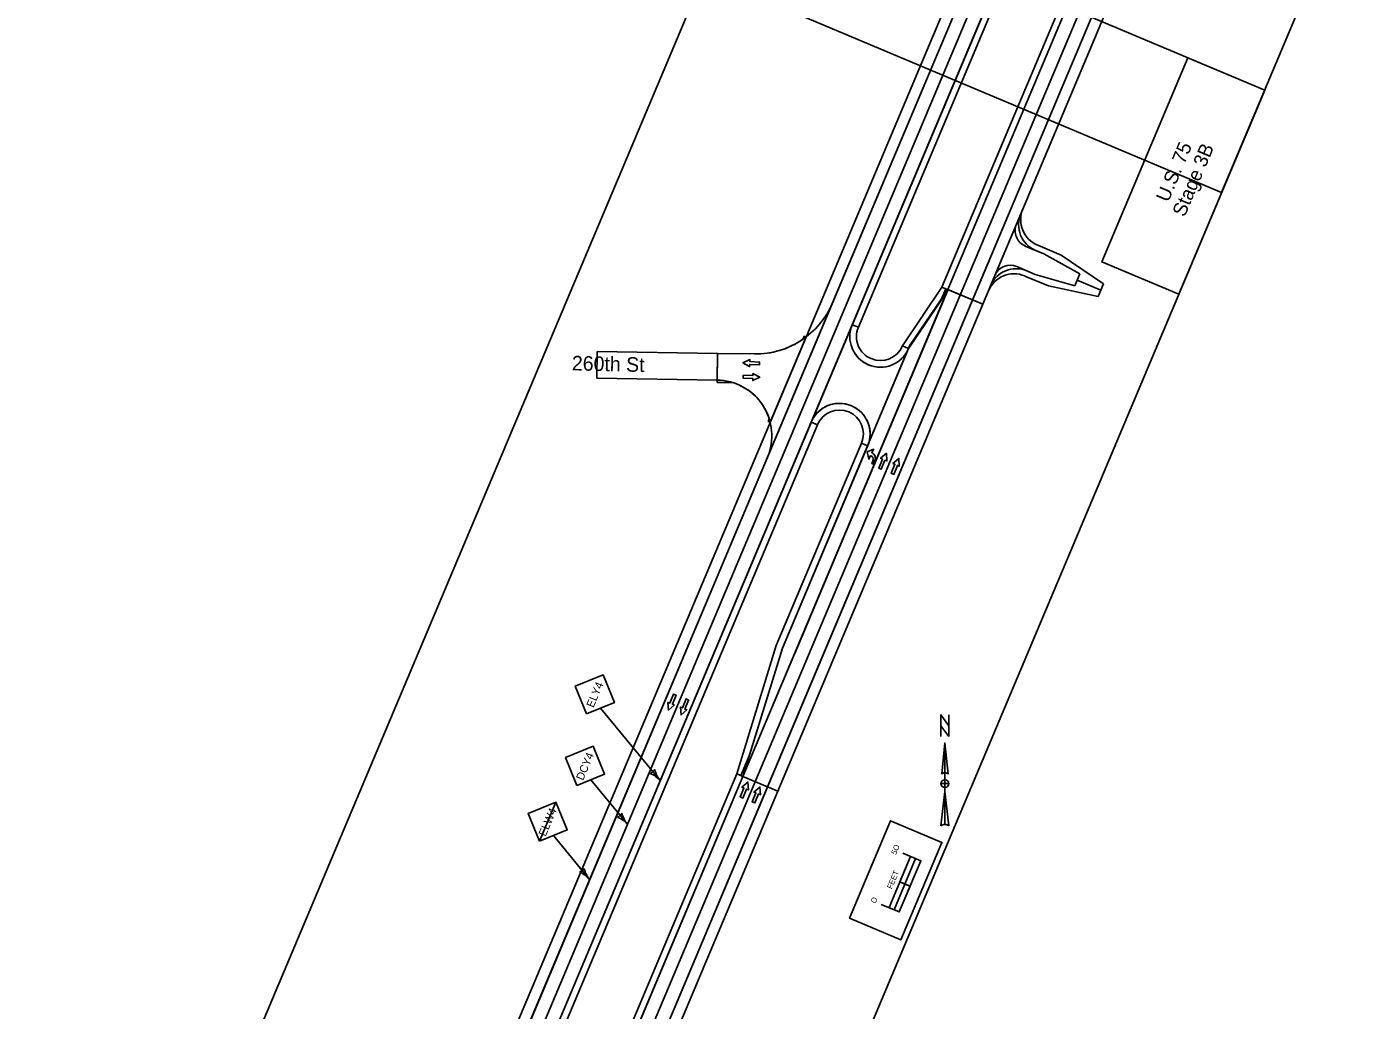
# Model space of a CAD drawing. Extents: x 14104283 to 14120882, y 8635219 to 8671666.
# Drawn here: x 14112889 to 14114078, y 8655411 to 8656296 of the extents above; entities that cross this region are included whole.
import ezdxf

# ---------------------------------------------------------------- set-up
doc = ezdxf.new("R2010")
doc.units = 0
for name, color, linetype in [('Cell', 7, 'Continuous'), ('dsnCellsNorthArrow', 7, 'Continuous'), ('dsnCellsScaleBlock', 7, 'Continuous'), ('dsnNonPlotable', 7, 'Continuous'), ('dsnPaintExistingBrokenLaneLineWhite', 7, 'Continuous'), ('dsnPaintExistingEdgeLineLeftYellow', 7, 'Continuous'), ('dsnPaintExistingEdgeLineRightWhite', 7, 'Continuous'), ('dsnPaintExistingLaneLineWhite', 7, 'Continuous'), ('dsnShadingGranular', 7, 'Continuous'), ('dsnShadingPaved', 7, 'Continuous'), ('dsnStdLabel', 7, 'Continuous'), ('dsnStgShadingPrevPav', 7, 'Continuous'), ('dsnTextFinalPlan', 7, 'Continuous'), ('dsnTextOverlapEven', 7, 'Continuous')]:
    doc.layers.add(name, color=color, linetype=linetype)

msp = doc.modelspace()

# ---------------------------------------------------------------- linework, layer by layer
at = {"layer": 'Cell'}
for p, q in [((14113648.5, 8655910.1), (14113648.2, 8655910.2)), ((14113649.3, 8655912.6), (14113649.4, 8655912.5))]:
    msp.add_line(p, q, dxfattribs=at)
for points in [[(14113548.3, 8655994.3), (14113548.2, 8655991.8), (14113539.5, 8655992.2), (14113539.4, 8655990.3), (14113533.3, 8655993.7), (14113539.7, 8655996.5), (14113539.6, 8655994.7)], [(14113533.5, 8655979.9), (14113533.6, 8655982.4), (14113542.3, 8655982.1), (14113542.4, 8655984), (14113548.5, 8655980.6), (14113542.2, 8655977.7), (14113542.2, 8655979.6)], [(14113657.8, 8655898), (14113655.5, 8655899), (14113658.8, 8655907.1), (14113657.1, 8655907.8), (14113662.4, 8655912.4), (14113662.9, 8655905.4), (14113661.1, 8655906.1)], [(14113669, 8655893.3), (14113666.7, 8655894.3), (14113670, 8655902.4), (14113668.3, 8655903.1), (14113673.5, 8655907.7), (14113674, 8655900.7), (14113672.3, 8655901.4)], [(14113470.9, 8655695.7), (14113473.2, 8655694.7), (14113469.9, 8655686.6), (14113471.6, 8655685.9), (14113466.3, 8655681.3), (14113465.8, 8655688.3), (14113467.5, 8655687.6)], [(14113482.2, 8655691.4), (14113484.5, 8655690.4), (14113481.2, 8655682.3), (14113482.9, 8655681.6), (14113477.7, 8655677), (14113477.1, 8655684), (14113478.9, 8655683.3)], [(14113533.3, 8655602.2), (14113530.9, 8655603.2), (14113534.3, 8655611.2), (14113532.5, 8655612), (14113537.8, 8655616.6), (14113538.3, 8655609.6), (14113536.6, 8655610.3)], [(14113544.1, 8655597.8), (14113541.7, 8655598.7), (14113545.1, 8655606.8), (14113543.3, 8655607.5), (14113548.6, 8655612.1), (14113549.1, 8655605.2), (14113547.4, 8655605.9)]]:
    msp.add_lwpolyline(points, close=True, dxfattribs=at)
for points in [[(14113539.6, 8655994.7), (14113539.7, 8655996.5), (14113533.3, 8655993.7), (14113539.4, 8655990.3), (14113539.5, 8655992.2), (14113548.2, 8655991.8), (14113548.3, 8655994.3), (14113539.6, 8655994.7)], [(14113542.2, 8655979.6), (14113542.2, 8655977.7), (14113548.5, 8655980.6), (14113542.4, 8655984), (14113542.3, 8655982.1), (14113533.6, 8655982.4), (14113533.5, 8655979.9), (14113542.2, 8655979.6)], [(14113645.1, 8655913.7), (14113650.8, 8655915.9), (14113649.3, 8655912.6)], [(14113645.1, 8655913.7), (14113650.8, 8655915.9), (14113649.3, 8655912.6)], [(14113648.2, 8655910.2), (14113646.6, 8655906.9), (14113645.1, 8655913.7)], [(14113648.2, 8655910.2), (14113646.6, 8655906.9), (14113645.1, 8655913.7)], [(14113648.5, 8655910.1), (14113648.2, 8655910.2)], [(14113649.3, 8655912.6), (14113649.4, 8655912.5)], [(14113661.1, 8655906.1), (14113662.9, 8655905.4), (14113662.4, 8655912.4), (14113657.1, 8655907.8), (14113658.8, 8655907.1), (14113655.5, 8655899), (14113657.8, 8655898), (14113661.1, 8655906.1)], [(14113652.1, 8655905.8), (14113650.7, 8655902.4), (14113649.3, 8655902.9), (14113650.3, 8655905.4)], [(14113652.1, 8655905.8), (14113650.7, 8655902.4), (14113649.3, 8655902.9), (14113650.3, 8655905.4)], [(14113672.3, 8655901.4), (14113674, 8655900.7), (14113673.5, 8655907.7), (14113668.3, 8655903.1), (14113670, 8655902.4), (14113666.7, 8655894.3), (14113669, 8655893.3), (14113672.3, 8655901.4)], [(14113467.5, 8655687.6), (14113465.8, 8655688.3), (14113466.3, 8655681.3), (14113471.6, 8655685.9), (14113469.9, 8655686.6), (14113473.2, 8655694.7), (14113470.9, 8655695.7), (14113467.5, 8655687.6)], [(14113478.9, 8655683.3), (14113477.1, 8655684), (14113477.7, 8655677), (14113482.9, 8655681.6), (14113481.2, 8655682.3), (14113484.5, 8655690.4), (14113482.2, 8655691.4), (14113478.9, 8655683.3)], [(14113536.6, 8655610.3), (14113538.3, 8655609.6), (14113537.8, 8655616.6), (14113532.5, 8655612), (14113534.3, 8655611.2), (14113530.9, 8655603.2), (14113533.3, 8655602.2), (14113536.6, 8655610.3)], [(14113547.4, 8655605.9), (14113549.1, 8655605.2), (14113548.6, 8655612.1), (14113543.3, 8655607.5), (14113545.1, 8655606.8), (14113541.7, 8655598.7), (14113544.1, 8655597.8), (14113547.4, 8655605.9)]]:
    msp.add_lwpolyline(points, dxfattribs=at)
for centre, major_axis in [((14113647.1, 8655906.7), (-1.38, -3.41)), ((14113647.1, 8655906.7), (-1.38, -3.41)), ((14113647.5, 8655907.7), (-1.97, -4.87)), ((14113647.5, 8655907.7), (-1.97, -4.87))]:
    msp.add_ellipse(centre, major_axis=major_axis, ratio=0.9474, start_param=1.570796, end_param=3.141593, dxfattribs=at)
at = {"layer": 'dsnCellsNorthArrow'}
for p, q in [((14113715, 8655651.8), (14113717.8, 8655623.7)), ((14113715, 8655651.8), (14113715, 8655578.6)), ((14113712.1, 8655623.7), (14113712.1, 8655623.7)), ((14113712.3, 8655623.9), (14113712.8, 8655624.5)), ((14113715, 8655611.7), (14113715, 8655611.7)), ((14113711.4, 8655577.2), (14113715, 8655608.2))]:
    msp.add_line(p, q, dxfattribs=at)
msp.add_lwpolyline([(14113718.5, 8655657.5), (14113711.4, 8655667.3), (14113711.4, 8655677.2), (14113718.5, 8655667.3)], close=True, dxfattribs=at)
for points in [[(14113711.4, 8655657.5), (14113711.4, 8655677.2), (14113718.5, 8655667.3), (14113718.5, 8655677.2)], [(14113712.1, 8655623.7), (14113715, 8655651.8), (14113715, 8655625.1)], [(14113715, 8655611.7), (14113715, 8655615.2), (14113711.4, 8655615.2)], [(14113718.5, 8655615.2), (14113715, 8655615.2), (14113715, 8655618.7)], [(14113715, 8655578.6), (14113715, 8655608.2), (14113718.5, 8655577.2)]]:
    msp.add_lwpolyline(points, dxfattribs=at)
for centre, radius, start, end in [((14113715, 8655621.5), 3.52, 90.0204, 143.1257), ((14113715, 8655621.5), 3.52, 36.8481, 90.0218), ((14113715, 8655615.2), 3.52, 90, 180), ((14113715, 8655615.2), 3.52, 180, 270), ((14113715, 8655615.2), 3.52, 0, 90), ((14113715, 8655615.2), 3.52, 270, 360), ((14113715, 8655573.5), 5.1, 89.9894, 133.619), ((14113715, 8655573.5), 5.11, 46.4021, 90.0006)]:
    msp.add_arc(centre, radius, start, end, dxfattribs=at)
at = {"layer": 'dsnCellsScaleBlock'}
msp.add_line((14113683.7, 8655522.9), (14113674.5, 8655526.8), dxfattribs=at)
msp.add_line((14113683.7, 8655522.9), (14113674.5, 8655526.8), dxfattribs=at)
for points in [[(14113675.4, 8655474.8), (14113629.3, 8655494.2), (14113666.2, 8655581.8), (14113712.3, 8655562.4)], [(14113629.3, 8655494.2), (14113666.2, 8655581.8), (14113712.3, 8655562.4), (14113675.4, 8655474.8)], [(14113675.4, 8655474.8), (14113629.3, 8655494.2), (14113666.2, 8655581.8), (14113712.3, 8655562.4)], [(14113679, 8655524.8), (14113688.7, 8655547.9), (14113684.2, 8655549.8), (14113674.5, 8655526.8)], [(14113674, 8655499.8), (14113683.7, 8655522.9), (14113679, 8655524.8), (14113669.3, 8655501.8)]]:
    msp.add_lwpolyline(points, close=True, dxfattribs=at)
for points in [[(14113657.8, 8655506.6), (14113674, 8655499.8), (14113693.4, 8655545.9), (14113677.3, 8655552.7)], [(14113664.8, 8655503.7), (14113684.2, 8655549.8)]]:
    msp.add_lwpolyline(points, dxfattribs=at)
at = {"layer": 'dsnNonPlotable'}
for points in [[(14113498.5, 8656342.8), (14114107.1, 8657787.4), (14114572.5, 8657591.3), (14113963.9, 8656146.8)], [(14112928.7, 8654990.5), (14113537.3, 8656435), (14114002.7, 8656238.9), (14113394.1, 8654794.4)]]:
    msp.add_lwpolyline(points, close=True, dxfattribs=at)
at = {"layer": 'dsnPaintExistingBrokenLaneLineWhite'}
for p, q in [((14110829.5, 8649404.5), (14118424.3, 8667439.6)), ((14110913.3, 8649369.2), (14114932.5, 8658913.4))]:
    msp.add_line(p, q, dxfattribs=at)
at = {"layer": 'dsnPaintExistingEdgeLineLeftYellow'}
for p, q in [((14115779.3, 8661127.7), (14113631.7, 8656027.9)), ((14113717.7, 8656059.5), (14115716.8, 8660806.7)), ((14113682.1, 8656006), (14113717.7, 8656059.5)), ((14113594.8, 8655940.3), (14111420.5, 8650777)), ((14113568.9, 8655737), (14113646.5, 8655921.3)), ((14113533.3, 8655621.7), (14113568.9, 8655737)), ((14111505.3, 8650805.9), (14113533.3, 8655621.7))]:
    msp.add_line(p, q, dxfattribs=at)
for centre, radius, start, end in [((14113657, 8656017.2), 27.5, 157.1633, 335.9016), ((14113620.2, 8655929.6), 27.6, 342.4922, 157.0396)]:
    msp.add_arc(centre, radius, start, end, dxfattribs=at)
at = {"layer": 'dsnPaintExistingEdgeLineRightWhite'}
for p, q in [((14110924.4, 8649364.5), (14118874.7, 8668243.7)), ((14115734.9, 8661084), (14113613.9, 8656047.5)), ((14113555.5, 8655908.7), (14111402.9, 8650797.1))]:
    msp.add_line(p, q, dxfattribs=at)
at = {"layer": 'dsnPaintExistingLaneLineWhite'}
msp.add_line((14113579.9, 8655732.3), (14113656.6, 8655914.3), dxfattribs=at)
at = {"layer": 'dsnShadingGranular'}
for p, q in [((14113783.2, 8656127.5), (14113779.3, 8656118.3)), ((14113779.3, 8656118.3), (14113759.9, 8656072.2)), ((14113759.9, 8656072.2), (14113756.1, 8656063))]:
    msp.add_line(p, q, dxfattribs=at)
at = {"layer": 'dsnShadingPaved'}
for p, q in [((14115738.9, 8660797.4), (14113555.5, 8655612.4)), ((14113717.7, 8656059.5), (14115716.8, 8660806.7)), ((14113533.3, 8655621.7), (14113717.7, 8656059.5)), ((14113717.5, 8656059), (14113533.3, 8655621.7)), ((14113682.1, 8656006), (14113717.2, 8656058.5)), ((14113555.5, 8655908.7), (14113613.9, 8656047.5)), ((14113594.8, 8655940.3), (14113631.7, 8656027.9)), ((14113510.5, 8656002.1), (14113510.1, 8655978.1)), ((14113543.7, 8656001.6), (14113510.5, 8656002.1)), ((14113568.9, 8655737), (14113645.5, 8655919)), ((14113533.3, 8655621.7), (14113568.9, 8655737)), ((14113555.5, 8655612.4), (14110924.4, 8649364.5)), ((14111505.5, 8650806.3), (14113533.3, 8655621.7)), ((14113533.3, 8655621.7), (14113555.5, 8655612.4)), ((14113555.5, 8655612.4), (14113533.3, 8655621.7))]:
    msp.add_line(p, q, dxfattribs=at)
for points in [[(14118413.2, 8667444.3), (14110818.4, 8649409.2), (14109142.6, 8645431.4)], [(14109164.7, 8645422.1), (14110840.5, 8649399.8), (14118435.4, 8667434.9)]]:
    msp.add_lwpolyline(points, dxfattribs=at)
for centre, radius, start, end in [((14113544.8, 8656076.6), 75, 269.1633, 337.1633), ((14113657, 8656017.2), 27.5, 157.1633, 247.1633), ((14113657, 8656017.2), 27.5, 247.1633, 335.9016), ((14113509.4, 8655928.1), 50, 337.1633, 89.1633), ((14113620.2, 8655929.7), 27.5, 67.1633, 157.1633), ((14113620.2, 8655929.7), 27.5, 337.1633, 67.1633)]:
    msp.add_arc(centre, radius, start, end, dxfattribs=at)
at = {"layer": 'dsnStdLabel'}
for p, q in [((14113405.3, 8655683), (14113459, 8655617.9)), ((14113396.5, 8655618.7), (14113429.5, 8655578.7)), ((14113350.4, 8655563.4), (14113365.2, 8655598.6)), ((14113362.9, 8655568.5), (14113395.5, 8655529))]:
    msp.add_line(p, q, dxfattribs=at)
for points in [[(14113392.8, 8655677.9), (14113417.8, 8655688.1), (14113407.6, 8655713.1), (14113382.6, 8655702.9)], [(14113384, 8655613.6), (14113409, 8655623.7), (14113398.8, 8655648.8), (14113373.8, 8655638.6)], [(14113350.4, 8655563.4), (14113375.4, 8655573.6), (14113365.2, 8655598.6), (14113340.2, 8655588.5)]]:
    msp.add_lwpolyline(points, close=True, dxfattribs=at)
for centre, radius, start, end in [((14113446.5, 8655632.5), 8.86, 292.8385, 328.307), ((14113441.6, 8655603), 22.9, 40.5727, 68.6439), ((14113476.5, 8655632.8), 22.9, 192.5015, 220.5728), ((14113417, 8655593.3), 8.86, 292.8385, 328.307), ((14113446.9, 8655593.6), 22.9, 192.5015, 220.5728), ((14113412.1, 8655563.8), 22.9, 40.5727, 68.6439), ((14113383, 8655543.6), 8.86, 292.8385, 328.307), ((14113378.1, 8655514.1), 22.9, 40.5727, 68.6439), ((14113413, 8655543.9), 22.9, 192.5015, 220.5728)]:
    msp.add_arc(centre, radius, start, end, dxfattribs=at)
at = {"layer": 'dsnStgShadingPrevPav'}
for p, q in [((14110809.2, 8649413), (14118404, 8667448.1)), ((14118413.2, 8667444.3), (14110818.4, 8649409.2)), ((14115779.3, 8661127.7), (14113631.7, 8656027.9)), ((14113613.9, 8656047.5), (14115734.9, 8661084)), ((14115711.3, 8660809.1), (14113712.2, 8656061.8)), ((14113749, 8656046.3), (14115748.2, 8660793.5)), ((14113783.2, 8656127.5), (14113779.3, 8656118.3)), ((14113785.2, 8656132.1), (14113783.2, 8656127.5)), ((14113779.3, 8656118.3), (14113759.9, 8656072.2)), ((14113803.9, 8656091.6), (14113787.3, 8656098.6)), ((14113787.3, 8656098.6), (14113796.6, 8656094.7)), ((14113819.7, 8656090.4), (14113798.5, 8656099.4)), ((14113796.6, 8656094.7), (14113803.9, 8656091.6)), ((14113836.4, 8656073.6), (14113803.9, 8656091.6)), ((14113803.9, 8656091.6), (14113836.4, 8656073.6)), ((14113857.7, 8656064.7), (14113819.7, 8656090.4)), ((14113779.6, 8656080.2), (14113796.2, 8656073.2)), ((14113788.8, 8656076.3), (14113779.6, 8656080.2)), ((14113796.2, 8656073.2), (14113788.8, 8656076.3)), ((14113756.1, 8656063), (14113754.1, 8656058.4)), ((14113759.9, 8656072.2), (14113756.1, 8656063)), ((14113786.9, 8656071.7), (14113808.1, 8656062.8)), ((14113796.2, 8656073.2), (14113831.9, 8656062.8)), ((14113831.9, 8656062.8), (14113796.2, 8656073.2)), ((14113808.1, 8656062.8), (14113852.9, 8656053.4)), ((14113831.9, 8656062.8), (14113836.4, 8656073.6)), ((14113834.1, 8656068.1), (14113831.9, 8656062.8)), ((14113836.4, 8656073.6), (14113834.1, 8656068.1)), ((14113855.3, 8656059.1), (14113834.1, 8656068.1)), ((14113834.1, 8656068.1), (14113855.3, 8656059.1)), ((14113855.3, 8656059.1), (14113857.7, 8656064.7)), ((14113712.2, 8656061.8), (14113749, 8656046.3)), ((14113852.9, 8656053.4), (14113855.3, 8656059.1)), ((14113555.5, 8655908.7), (14113613.9, 8656047.5)), ((14113594.8, 8655940.3), (14113631.7, 8656027.9)), ((14113631.7, 8656027.9), (14113594.8, 8655940.3)), ((14113631.7, 8656027.9), (14113637.2, 8656025.6)), ((14113590.2, 8656016.9), (14113557.9, 8655940.2)), ((14113587.1, 8656014.7), (14113588.3, 8656017.7)), ((14113588.3, 8656017.7), (14113590.2, 8656016.9)), ((14113682.4, 8656006.5), (14113645.5, 8655919)), ((14113676.8, 8656008.9), (14113682.4, 8656006.5)), ((14113510.1, 8655976.1), (14113510.5, 8656002.1)), ((14113510.5, 8656002.1), (14113543.7, 8656001.6)), ((14113524.1, 8655975.9), (14113510.1, 8655976.1)), ((14113594.8, 8655940.3), (14111420.5, 8650777)), ((14113556, 8655941), (14113557, 8655943.3)), ((14113557.9, 8655940.2), (14113556, 8655941)), ((14113600.3, 8655938), (14113594.8, 8655940.3)), ((14113645.5, 8655919), (14113640, 8655921.3)), ((14111402.9, 8650797.1), (14113555.5, 8655908.7)), ((14113533.3, 8655621.7), (14111505.5, 8650806.3)), ((14113564.7, 8655608.5), (14113533.3, 8655621.7)), ((14111352.5, 8650355.3), (14113564.7, 8655608.5))]:
    msp.add_line(p, q, dxfattribs=at)
for points in [[(14115784.8, 8661125.3), (14113637.2, 8656025.6), (14113631.7, 8656027.9), (14115779.3, 8661127.7)], [(14113533.3, 8655621.7), (14113531.5, 8655622.5), (14113539.3, 8655640.9), (14113568.9, 8655737), (14113683.3, 8656008.9), (14113712, 8656051.1), (14113715.8, 8656060.3), (14113717.7, 8656059.5)], [(14113533.3, 8655621.7), (14113717.7, 8656059.5), (14113749, 8656046.3), (14113564.7, 8655608.5)], [(14113676.8, 8656008.9), (14113712.2, 8656061.8), (14113715.8, 8656060.3), (14113712, 8656051.1), (14113683.3, 8656008.9), (14113682.4, 8656006.5)], [(14113402, 8655979.7), (14113402.4, 8656003.7), (14113510.5, 8656002.1), (14113510.1, 8655978.1)], [(14113600.3, 8655938), (14111426, 8650774.7), (14111420.5, 8650777), (14113594.8, 8655940.3)], [(14113527.8, 8655624.1), (14113563.3, 8655739.3), (14113640, 8655921.3), (14113645.5, 8655919), (14113568.9, 8655737), (14113539.3, 8655640.9), (14113531.5, 8655622.5)], [(14111465.6, 8650758), (14111500, 8650808.6), (14113527.8, 8655624.1), (14113533.3, 8655621.7), (14111505.5, 8650806.3), (14111503.6, 8650807.1), (14111499.8, 8650797.8), (14111471.1, 8650755.6)]]:
    msp.add_lwpolyline(points, close=True, dxfattribs=at)
for centre, radius, start, end in [((14113806.3, 8656117.8), 25, 157.1633, 247.1633), ((14113806.3, 8656117.8), 25, 157.1633, 247.1633), ((14113808.2, 8656122.4), 25, 157.1651, 247.1633), ((14113793.2, 8656112.5), 15, 157.1633, 247.1633), ((14113793.2, 8656112.5), 15, 157.1633, 247.1633), ((14113779.1, 8656053.3), 25, 67.1633, 157.1633), ((14113779.1, 8656053.3), 25, 67.1633, 157.1633), ((14113773.8, 8656066.4), 15, 67.1633, 157.1633), ((14113773.8, 8656066.4), 15, 67.1633, 157.1633), ((14113777.2, 8656048.7), 25, 67.1633, 157.1619), ((14113657, 8656017.2), 21.5, 157.1633, 247.1633), ((14113544.8, 8656076.6), 75, 269.1633, 304.3034), ((14113657, 8656017.2), 21.5, 247.1633, 337.1633), ((14113509.4, 8655928.1), 50, 17.6991, 72.9031), ((14113620.2, 8655929.7), 21.5, 67.1633, 157.1633), ((14113620.2, 8655929.7), 21.5, 337.1633, 67.1633)]:
    msp.add_arc(centre, radius, start, end, dxfattribs=at)
at = {"layer": 'dsnTextOverlapEven'}
for points in [[(14114002.7, 8656238.9), (14113925.3, 8656055.3), (14113856.2, 8656084.4), (14113933.6, 8656268)], [(14113856.2, 8656084.4), (14113933.6, 8656268), (14114002.7, 8656238.9), (14113925.3, 8656055.3)]]:
    msp.add_lwpolyline(points, close=True, dxfattribs=at)

# ---------------------------------------------------------------- texts
at = {"layer": 'dsnCellsScaleBlock'}
for s, p in [('5O', (14113671.1, 8655550.9)), ('FEET', (14113667.3, 8655520)), ('O', (14113652.6, 8655507.1))]:
    msp.add_text(s, height=5, rotation=67.1547, dxfattribs=at).set_placement(p)
at = {"layer": 'dsnStdLabel'}
for s, p in [('ELY4', (14113398.9, 8655683)), ('DCY4', (14113389.6, 8655617.6)), ('ELW4', (14113355.9, 8655567.2))]:
    msp.add_text(s, height=7.2, rotation=67.1547, dxfattribs=at).set_placement(p)
at = {"layer": 'dsnTextFinalPlan'}
msp.add_text('260th St', height=13.12, rotation=358.6374, dxfattribs=at).set_placement((14113379.4, 8655986.9))
at = {"layer": 'dsnTextOverlapEven'}
for s, p in [('U.S. 75', (14113915.9, 8656137.4)), ('Stage 3B', (14113930.6, 8656124.2))]:
    msp.add_text(s, height=12.5, rotation=67.1547, dxfattribs=at).set_placement(p)

doc.saveas('drawing.dxf')
